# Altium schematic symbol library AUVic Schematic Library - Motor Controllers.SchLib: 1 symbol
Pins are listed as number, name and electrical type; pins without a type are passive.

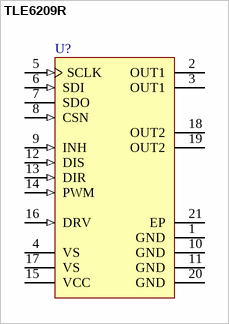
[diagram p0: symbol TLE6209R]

## TLE6209R
designator U?
7 A H-Bridge for DC-Motor Applications, 5.2 to 40 V, 140 mOhm RDS(on), PG-DSO-20-37, Reel, Green; Manufacturer: Infineon; PartNumber: TLE6209R; Current Limit (min.): 5.95 A; Green: TRUE; Quiescent Current (max.): 50 uA; RthJC (max): 1.5 K/W
footprint INF-PG-DSO-20-37_N (SOP, 20-Leads, Body 15.9x11mm, Pitch 1.27mm, Thermal Pad 15.84x6mm, IPC Medium Density)
footprint INF-PG-DSO-20-37_L (SOP, 20-Leads, Body 15.9x11mm, Pitch 1.27mm, Thermal Pad 15.84x6mm, IPC High Density)
footprint INF-PG-DSO-20-37_M (SOP, 20-Leads, Body 15.9x11mm, Pitch 1.27mm, Thermal Pad 15.84x6mm, IPC Low Density)
pins: 1 GND (power) "Ground; internally connected to cooling tab (heat slug); to reduce  thermal resistance place cooling areas and thermal vias on PCB.", 2 OUT1 (power) "Output 1; output of D-MOS half bridge 1; external connection  between pin 2 and pin 3 is necessary.", 3 OUT1 (power) "Output 1; output of D-MOS half bridge 1; external connection  between pin 2 and pin 3 is necessary.", 4 VS (power) "Power supply; needs a blocking capacitor as close as possible to  GND; 47 uF electrolytic in parallel to 220 nF ceramic is  recommended; external connection between pin 4 and pin 17 is  necessary.", 5 SCLK (in) "Serial clock input; clocks the shiftregister; SCLK has an internal  active pull down and requires CMOS logic levels", 6 SDI (in) "Serial data input; receives serial data from the control device;  serial data transmitted to SDI is an 8 bit control word with the Least  Significant Bit (LSB) being transferred first; the input has an active  pull down and (See Datasheet)", 7 SDO (hiz) "Serial-Data-Output; this tri-state output transfers diagnosis data to  the control device; the output will remain tri-stated unless the device  is selected by a low on Chip-Select-Not (CSN); SDO state changes  on the rising (See Datasheet)", 8 CSN (in) "Chip-Select-Not input; CSN is an active low input; serial  communication is enabled by pulling the CSN terminal low; CSN  input should only be transitioned when SCLK is low; CSN has an  internal active pull up and requires (See Datasheet)", 9 INH (in) "Inhibit input; has an internal pull down; device is switched in  standby condition by pulling the INH terminal low.", 10 GND (power) "Ground; internally connected to cooling tab (heat slug); to reduce  thermal resistance place cooling areas and thermal vias on PCB.", 11 GND (power) "Ground; internally connected to cooling tab (heat slug); to reduce  thermal resistance place cooling areas and thermal vias on PCB.", 12 DIS (in) "Disable input; has an internal pull up; the output stages are  switched in tristate condition by pulling the DIS terminal high", 13 DIR (in) "Direction input; has an internal pull down; TTL/CMOS compatible  input", 14 PWM (in) "PWM input; has an internal pull down; TTL/CMOS compatible  input.", 15 VCC (power) "Logic supply voltage; needs a blocking capacitor as close as  possible to GND; 10 uF electrolytic in parallel to 220 nF ceramic is  recommended.", 16 DRV (in) "Drive; Input for external charge pump capacitor CDRV", 17 VS (power) "Power supply; needs a blocking capacitor as close as possible to  GND; 47 uF electrolytic in parallel to 220 nF ceramic is  recommended; external connection between pin 4 and pin 17 is  necessary.", 18 OUT2 (power) "Output 2; output of D-MOS half bridge 2; external connection  between pin 2 and pin 3 is necessary.", 19 OUT2 (power) "Output 2; output of D-MOS half bridge 2; external connection  between pin 2 and pin 3 is necessary.", 20 GND (power) "Ground; internally connected to cooling tab (heat slug); to reduce  thermal resistance place cooling areas and thermal vias on PCB.", 21 EP (power)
